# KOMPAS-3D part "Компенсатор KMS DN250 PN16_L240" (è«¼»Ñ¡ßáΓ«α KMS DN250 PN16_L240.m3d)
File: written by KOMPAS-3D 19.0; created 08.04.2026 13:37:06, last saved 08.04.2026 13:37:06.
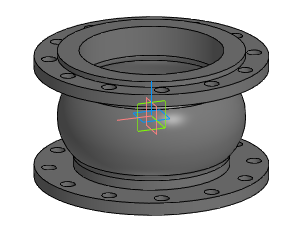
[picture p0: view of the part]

Document properties: Автор: Энергия; Полное имя файла: Z:\3.Личные\kachalov\3d для проектировщиков\7.1 Компенсатор\stp_Компенсатор KSM\Компенсатор KMS DN250 PN16_L240.m3d

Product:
- Part/product: Компенсатор KMS DN250 PN16_L240

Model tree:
1. Операция без истории:1  (labels: Компенсатор KMS DN250 PN16_L240)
